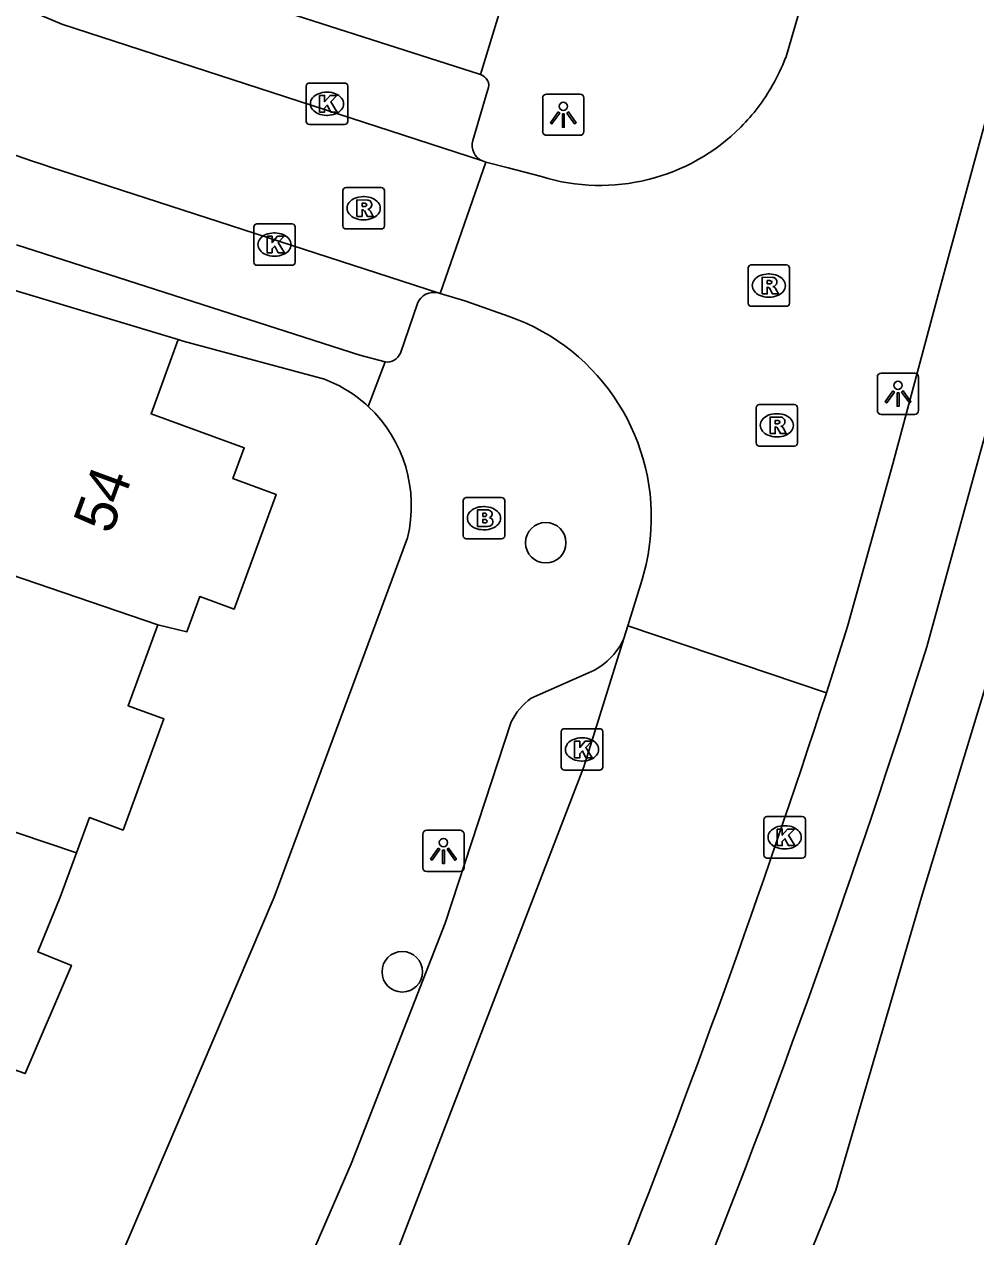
# Model space of a CAD drawing. Extents: x 162542 to 163144, y 380786 to 381511.
# Drawn here: x 163065.29 to 163088.28, y 380991.8 to 381021.08 of the extents above; entities that cross this region are included whole.
import ezdxf

# ---------------------------------------------------------------- set-up
doc = ezdxf.new("R2010")
doc.units = 0
for name, color, linetype in [('IMGEO_Berm_groen', 7, 'Continuous'), ('IMGEO_Boom', 7, 'Continuous'), ('IMGEO_Brandkraan', 7, 'Continuous'), ('IMGEO_Kolk', 7, 'Continuous'), ('IMGEO_Lichtpunt', 7, 'Continuous'), ('IMGEO_Pand', 7, 'Continuous'), ('IMGEO_Pand_nummerreeks', 7, 'Continuous'), ('IMGEO_Parkeervlak_open', 7, 'Continuous'), ('IMGEO_Rijbaan_lokaal_open', 7, 'Continuous'), ('IMGEO_Rioolput', 7, 'Continuous'), ('IMGEO_Voetpad_open', 7, 'Continuous')]:
    doc.layers.add(name, color=color, linetype=linetype)

msp = doc.modelspace()

# ---------------------------------------------------------------- linework, layer by layer
at = {"layer": 'IMGEO_Berm_groen'}
msp.add_lwpolyline([(163077.516, 380959.974), (163074.43, 380965.619), (163074.1, 380966.465), (163073.95, 380967.815), (163074.225, 380969.146), (163074.714, 380970.08), (163079.391, 380979.871), (163082.225, 380986.346), (163084.894, 380992.933), (163086.964, 381000), (163089.194, 381007.335), (163094.981, 381005.761)], dxfattribs=at)
at = {"layer": 'IMGEO_Boom'}
for centre in [(163077.888, 381008.559), (163074.424, 380998.201)]:
    msp.add_circle(centre, 0.489, dxfattribs=at)
at = {"layer": 'IMGEO_Brandkraan'}
for p, q in [((163075.896, 381008.725), (163075.896, 381009.577)), ((163075.971, 381009.651), (163076.823, 381009.651)), ((163076.897, 381009.577), (163076.897, 381008.725)), ((163076.384, 381009.431), (163076.409, 381009.431)), ((163076.823, 381008.651), (163075.971, 381008.651)), ((163076.407, 381008.871), (163076.382, 381008.871))]:
    msp.add_line(p, q, dxfattribs=at)
for points in [[(163075.896, 381008.725), (163075.896, 381009.577)], [(163075.971, 381009.651), (163076.823, 381009.651)], [(163076.897, 381009.577), (163076.897, 381008.725)], [(163076.244, 381009.351), (163076.244, 381008.951), (163076.457, 381008.951)], [(163076.475, 381009.351), (163076.244, 381009.351)], [(163076.423, 381009.27), (163076.369, 381009.27), (163076.369, 381009.194)], [(163076.369, 381009.194), (163076.422, 381009.194)], [(163076.431, 381009.118), (163076.369, 381009.118), (163076.369, 381009.037)], [(163076.369, 381009.037), (163076.431, 381009.037)], [(163076.823, 381008.651), (163075.971, 381008.651)]]:
    msp.add_lwpolyline(points, dxfattribs=at)
for centre, radius, start, end in [((163075.973, 381009.575), 0.0765, 91.552, 178.448), ((163075.973, 381009.575), 0.0765, 91.552, 178.448), ((163076.821, 381009.575), 0.0765, 1.552, 88.448), ((163076.821, 381009.575), 0.0765, 1.552, 88.448), ((163076.424, 381009.232), 0.0379, 267.8285, 90.9355), ((163076.479, 381009.206), 0.145, 59.4692, 91.5367), ((163076.504, 381009.253), 0.0922, 285.5137, 58.1501), ((163076.432, 381009.077), 0.0404, 269.8759, 90.5077), ((163076.463, 381009.202), 0.251, 268.6676, 293.5347), ((163076.509, 381009.061), 0.105, 301.3115, 78.989), ((163075.973, 381008.727), 0.0765, 181.552, 268.448), ((163075.973, 381008.727), 0.0765, 181.552, 268.448), ((163076.821, 381008.727), 0.0765, 271.552, 358.448), ((163076.821, 381008.727), 0.0765, 271.552, 358.448)]:
    msp.add_arc(centre, radius, start, end, dxfattribs=at)
for centre, major_axis, ratio, start_param, end_param in [((163076.383, 381009.151), (-0.387, 0.002), 0.722429, 4.712389, 7.853982), ((163076.408, 381009.151), (-0.39, 0.002), 0.717154, 1.570796, 4.712389)]:
    msp.add_ellipse(centre, major_axis=major_axis, ratio=ratio, start_param=start_param, end_param=end_param, dxfattribs=at)
at = {"layer": 'IMGEO_Kolk'}
for p, q in [((163072.105, 381018.729), (163072.105, 381019.581)), ((163072.18, 381019.655), (163073.032, 381019.655)), ((163073.106, 381019.581), (163073.106, 381018.729)), ((163072.593, 381019.435), (163072.618, 381019.435)), ((163073.032, 381018.655), (163072.18, 381018.655)), ((163072.616, 381018.875), (163072.591, 381018.875)), ((163070.912, 381016.257), (163071.764, 381016.257)), ((163070.837, 381015.331), (163070.837, 381016.183)), ((163071.325, 381016.037), (163071.35, 381016.037)), ((163071.838, 381016.183), (163071.838, 381015.331)), ((163071.348, 381015.477), (163071.323, 381015.477)), ((163071.764, 381015.257), (163070.912, 381015.257)), ((163078.265, 381003.142), (163078.265, 381003.994)), ((163078.34, 381004.068), (163079.192, 381004.068)), ((163079.266, 381003.994), (163079.266, 381003.142)), ((163078.753, 381003.848), (163078.778, 381003.848)), ((163078.776, 381003.288), (163078.751, 381003.288)), ((163079.192, 381003.068), (163078.34, 381003.068)), ((163083.233, 381001.947), (163084.085, 381001.947)), ((163083.158, 381001.021), (163083.158, 381001.873)), ((163083.646, 381001.727), (163083.671, 381001.727)), ((163084.159, 381001.873), (163084.159, 381001.021)), ((163083.669, 381001.167), (163083.644, 381001.167)), ((163084.085, 381000.947), (163083.233, 381000.947))]:
    msp.add_line(p, q, dxfattribs=at)
for points in [[(163072.105, 381018.729), (163072.105, 381019.581)], [(163072.18, 381019.655), (163073.032, 381019.655)], [(163073.106, 381019.581), (163073.106, 381018.729)], [(163072.426, 381019.355), (163072.549, 381019.355), (163072.549, 381019.204), (163072.679, 381019.355), (163072.843, 381019.355), (163072.697, 381019.204), (163072.85, 381018.955), (163072.698, 381018.955), (163072.613, 381019.119), (163072.549, 381019.052), (163072.549, 381018.955), (163072.426, 381018.955), (163072.426, 381019.355)], [(163073.032, 381018.655), (163072.18, 381018.655)], [(163070.912, 381016.257), (163071.764, 381016.257)], [(163070.837, 381015.331), (163070.837, 381016.183)], [(163071.158, 381015.957), (163071.281, 381015.957), (163071.281, 381015.806), (163071.411, 381015.957), (163071.575, 381015.957), (163071.429, 381015.806), (163071.582, 381015.557), (163071.43, 381015.557), (163071.345, 381015.721), (163071.281, 381015.654), (163071.281, 381015.557), (163071.158, 381015.557), (163071.158, 381015.957)], [(163071.838, 381016.183), (163071.838, 381015.331)], [(163071.764, 381015.257), (163070.912, 381015.257)], [(163078.265, 381003.142), (163078.265, 381003.994)], [(163078.34, 381004.068), (163079.192, 381004.068)], [(163079.266, 381003.994), (163079.266, 381003.142)], [(163078.586, 381003.768), (163078.709, 381003.768), (163078.709, 381003.617), (163078.839, 381003.768), (163079.003, 381003.768), (163078.857, 381003.617), (163079.01, 381003.368), (163078.858, 381003.368), (163078.773, 381003.532), (163078.709, 381003.465), (163078.709, 381003.368), (163078.586, 381003.368), (163078.586, 381003.768)], [(163079.192, 381003.068), (163078.34, 381003.068)], [(163083.233, 381001.947), (163084.085, 381001.947)], [(163083.158, 381001.021), (163083.158, 381001.873)], [(163083.479, 381001.647), (163083.602, 381001.647), (163083.602, 381001.496), (163083.732, 381001.647), (163083.896, 381001.647), (163083.75, 381001.496), (163083.903, 381001.247), (163083.751, 381001.247), (163083.666, 381001.411), (163083.602, 381001.344), (163083.602, 381001.247), (163083.479, 381001.247), (163083.479, 381001.647)], [(163084.159, 381001.873), (163084.159, 381001.021)], [(163084.085, 381000.947), (163083.233, 381000.947)]]:
    msp.add_lwpolyline(points, dxfattribs=at)
for centre, start, end in [((163072.182, 381019.579), 91.552, 178.448), ((163072.182, 381019.579), 91.552, 178.448), ((163073.03, 381019.579), 1.552, 88.448), ((163073.03, 381019.579), 1.552, 88.448), ((163072.182, 381018.731), 181.552, 268.448), ((163072.182, 381018.731), 181.552, 268.448), ((163073.03, 381018.731), 271.552, 358.448), ((163073.03, 381018.731), 271.552, 358.448), ((163070.914, 381016.181), 91.552, 178.448), ((163070.914, 381016.181), 91.552, 178.448), ((163071.762, 381016.181), 1.552, 88.448), ((163071.762, 381016.181), 1.552, 88.448), ((163070.914, 381015.333), 181.552, 268.448), ((163070.914, 381015.333), 181.552, 268.448), ((163071.762, 381015.333), 271.552, 358.448), ((163071.762, 381015.333), 271.552, 358.448), ((163078.342, 381003.992), 91.552, 178.448), ((163078.342, 381003.992), 91.552, 178.448), ((163079.19, 381003.992), 1.552, 88.448), ((163079.19, 381003.992), 1.552, 88.448), ((163078.342, 381003.144), 181.552, 268.448), ((163078.342, 381003.144), 181.552, 268.448), ((163079.19, 381003.144), 271.552, 358.448), ((163079.19, 381003.144), 271.552, 358.448), ((163083.235, 381001.871), 91.552, 178.448), ((163083.235, 381001.871), 91.552, 178.448), ((163084.083, 381001.871), 1.552, 88.448), ((163084.083, 381001.871), 1.552, 88.448), ((163083.235, 381001.023), 181.552, 268.448), ((163083.235, 381001.023), 181.552, 268.448), ((163084.083, 381001.023), 271.552, 358.448), ((163084.083, 381001.023), 271.552, 358.448)]:
    msp.add_arc(centre, 0.0765, start, end, dxfattribs=at)
for centre, major_axis, ratio, start_param, end_param in [((163072.592, 381019.155), (-0.387, 0.002), 0.722429, 4.712389, 7.853982), ((163072.617, 381019.155), (-0.39, 0.002), 0.717154, 1.570796, 4.712389), ((163071.324, 381015.757), (-0.387, 0.002), 0.722429, 4.712389, 7.853982), ((163071.349, 381015.757), (-0.39, 0.002), 0.717154, 1.570796, 4.712389), ((163078.752, 381003.568), (-0.387, 0.002), 0.722429, 4.712389, 7.853982), ((163078.777, 381003.568), (-0.39, 0.002), 0.717154, 1.570796, 4.712389), ((163083.645, 381001.447), (-0.387, 0.002), 0.722429, 4.712389, 7.853982), ((163083.67, 381001.447), (-0.39, 0.002), 0.717154, 1.570796, 4.712389)]:
    msp.add_ellipse(centre, major_axis=major_axis, ratio=ratio, start_param=start_param, end_param=end_param, dxfattribs=at)
at = {"layer": 'IMGEO_Lichtpunt'}
for p, q in [((163077.815, 381019.295), (163077.815, 381018.488)), ((163077.815, 381019.295), (163077.815, 381018.488)), ((163078.717, 381019.39), (163077.909, 381019.39)), ((163078.717, 381019.39), (163077.909, 381019.39)), ((163078.811, 381018.488), (163078.811, 381019.295)), ((163078.811, 381018.488), (163078.811, 381019.295)), ((163077.909, 381018.394), (163078.717, 381018.394)), ((163077.909, 381018.394), (163078.717, 381018.394)), ((163085.899, 381012.559), (163085.899, 381011.752)), ((163085.899, 381012.559), (163085.899, 381011.752)), ((163086.801, 381012.654), (163085.993, 381012.654)), ((163086.801, 381012.654), (163085.993, 381012.654)), ((163086.895, 381011.752), (163086.895, 381012.559)), ((163086.895, 381011.752), (163086.895, 381012.559)), ((163085.993, 381011.658), (163086.801, 381011.658)), ((163085.993, 381011.658), (163086.801, 381011.658)), ((163075.821, 381001.617), (163075.013, 381001.617)), ((163075.821, 381001.617), (163075.013, 381001.617)), ((163074.919, 381001.522), (163074.919, 381000.715)), ((163074.919, 381001.522), (163074.919, 381000.715)), ((163075.915, 381000.715), (163075.915, 381001.522)), ((163075.915, 381000.715), (163075.915, 381001.522)), ((163075.013, 381000.621), (163075.821, 381000.621)), ((163075.013, 381000.621), (163075.821, 381000.621))]:
    msp.add_line(p, q, dxfattribs=at)
for points in [[(163078.189, 381018.959), (163078.228, 381018.931), (163078.04, 381018.669), (163078.002, 381018.696), (163078.189, 381018.959)], [(163078.291, 381018.911), (163078.338, 381018.911), (163078.338, 381018.589), (163078.291, 381018.589), (163078.291, 381018.911)], [(163078.401, 381018.931), (163078.439, 381018.958), (163078.626, 381018.696), (163078.587, 381018.668), (163078.401, 381018.931)], [(163086.273, 381012.223), (163086.312, 381012.195), (163086.124, 381011.933), (163086.086, 381011.96), (163086.273, 381012.223)], [(163086.375, 381012.175), (163086.422, 381012.175), (163086.422, 381011.853), (163086.375, 381011.853), (163086.375, 381012.175)], [(163086.485, 381012.195), (163086.523, 381012.222), (163086.71, 381011.96), (163086.671, 381011.932), (163086.485, 381012.195)], [(163075.293, 381001.186), (163075.332, 381001.158), (163075.144, 381000.896), (163075.106, 381000.923), (163075.293, 381001.186)], [(163075.395, 381001.138), (163075.442, 381001.138), (163075.442, 381000.816), (163075.395, 381000.816), (163075.395, 381001.138)], [(163075.505, 381001.158), (163075.543, 381001.185), (163075.73, 381000.923), (163075.691, 381000.895), (163075.505, 381001.158)]]:
    msp.add_lwpolyline(points, dxfattribs=at)
for centre in [(163078.314, 381019.093), (163086.398, 381012.357), (163075.418, 381001.32)]:
    msp.add_circle(centre, 0.0994, dxfattribs=at)
for centre, start, end in [((163077.909, 381019.295), 90, 180), ((163077.909, 381019.295), 90, 180), ((163078.717, 381019.295), 0, 90), ((163078.717, 381019.295), 0, 90), ((163077.909, 381018.488), 180, 270), ((163077.909, 381018.488), 180, 270), ((163078.717, 381018.488), 270, 0), ((163078.717, 381018.488), 270, 360), ((163085.993, 381012.559), 90, 180), ((163085.993, 381012.559), 90, 180), ((163086.801, 381012.559), 0, 90), ((163086.801, 381012.559), 0, 90), ((163085.993, 381011.752), 180, 270), ((163085.993, 381011.752), 180, 270), ((163086.801, 381011.752), 270, 0), ((163086.801, 381011.752), 270, 360), ((163075.013, 381001.522), 90, 180), ((163075.013, 381001.522), 90, 180), ((163075.821, 381001.522), 0, 90), ((163075.821, 381001.522), 0, 90), ((163075.013, 381000.715), 180, 270), ((163075.013, 381000.715), 180, 270), ((163075.821, 381000.715), 270, 0), ((163075.821, 381000.715), 270, 360)]:
    msp.add_arc(centre, 0.0946, start, end, dxfattribs=at)
at = {"layer": 'IMGEO_Pand'}
for points in [[(163058.425, 381016.641), (163059.788, 381016.232), (163069.013, 381013.461)], [(163068.518, 381006.576), (163069.221, 381006.408), (163069.534, 381007.26), (163070.362, 381006.956), (163071.38, 381009.724), (163070.334, 381010.108), (163070.605, 381010.846), (163068.355, 381011.673), (163069.013, 381013.461)], [(163057.81, 381010.232), (163068.518, 381006.576)], [(163068.518, 381006.576), (163067.8, 381004.624), (163068.668, 381004.305), (163067.682, 381001.622), (163066.867, 381001.922), (163066.554, 381001.07)], [(163055.826, 381004.685), (163066.554, 381001.07)], [(163066.554, 381001.07), (163066.16, 381000), (163065.623, 380998.68), (163066.431, 380998.356), (163065.317, 380995.743), (163064.6, 380995.997), (163064.442, 380995.619)]]:
    msp.add_lwpolyline(points, dxfattribs=at)
at = {"layer": 'IMGEO_Parkeervlak_open'}
msp.add_lwpolyline([(163089.453, 381014.635), (163089.294, 381014.047), (163088.512, 381011.194), (163087.092, 381006.049)], dxfattribs=at)
msp.add_arc((162878.42, 381071.645), 218.74, 338.09649, 342.5496, dxfattribs=at)
at = {"layer": 'IMGEO_Rijbaan_lokaal_open'}
for points in [[(163084.522, 381023.155), (163083.684, 381020.268)], [(163084.668, 381004.939), (163085.179, 381006.534), (163086.271, 381010.462), (163087.365, 381014.541), (163089.373, 381021.916)], [(163066.198, 381021.075), (163076.358, 381017.775)], [(163076.443, 381017.747), (163075.34, 381014.574)], [(163076.358, 381017.775), (163076.443, 381017.747)], [(163077.789, 381017.396), (163076.984, 381017.606), (163076.443, 381017.747)], [(163066.18, 381017.547), (163075.29, 381014.59)], [(163075.34, 381014.574), (163075.29, 381014.59)], [(163075.34, 381014.574), (163075.933, 381014.401), (163076.094, 381014.344), (163077.006, 381014.021)], [(163080.215, 381007.669), (163079.872, 381006.55)], [(163079.779, 381006.247), (163079.872, 381006.55)], [(163079.872, 381006.55), (163084.668, 381004.939)], [(163079.779, 381006.247), (163078.808, 381003.149), (163072.993, 380988.071)]]:
    msp.add_lwpolyline(points, dxfattribs=at)
for centre, radius, start, end in [((163077.641, 381048.539), 29.753, 219.7527, 247.3802), ((163074.034, 381042.707), 26.358, 235.8787, 252.6631), ((163079.133, 381022.02), 4.876, 330.2987, 338.9422), ((163079.289, 381021.913), 4.688, 314.9339, 330.4958), ((163079.2, 381021.989), 4.805, 252.9213, 315.0447), ((163075.297, 381009.171), 5.142, 354.1044, 70.5895), ((163075.289, 381009.172), 5.15, 343.0291, 354.1022), ((162863.597, 381076.707), 232.428, 338.26932, 342.01453)]:
    msp.add_arc(centre, radius, start, end, dxfattribs=at)
at = {"layer": 'IMGEO_Rioolput'}
for p, q in [((163073.066, 381017.134), (163073.918, 381017.134)), ((163072.991, 381016.208), (163072.991, 381017.06)), ((163073.479, 381016.914), (163073.504, 381016.914)), ((163073.992, 381017.06), (163073.992, 381016.208)), ((163073.502, 381016.354), (163073.477, 381016.354)), ((163073.918, 381016.134), (163073.066, 381016.134)), ((163082.777, 381014.341), (163082.777, 381015.193)), ((163082.852, 381015.267), (163083.704, 381015.267)), ((163083.778, 381015.193), (163083.778, 381014.341)), ((163083.265, 381015.047), (163083.29, 381015.047)), ((163083.288, 381014.487), (163083.263, 381014.487)), ((163083.704, 381014.267), (163082.852, 381014.267)), ((163083.045, 381011.893), (163083.897, 381011.893)), ((163082.97, 381010.967), (163082.97, 381011.819)), ((163083.458, 381011.673), (163083.483, 381011.673)), ((163083.971, 381011.819), (163083.971, 381010.967)), ((163083.481, 381011.113), (163083.456, 381011.113)), ((163083.897, 381010.893), (163083.045, 381010.893))]:
    msp.add_line(p, q, dxfattribs=at)
for points in [[(163073.066, 381017.134), (163073.918, 381017.134)], [(163072.991, 381016.208), (163072.991, 381017.06)], [(163073.58, 381016.832), (163073.328, 381016.834), (163073.328, 381016.434)], [(163073.992, 381017.06), (163073.992, 381016.208)], [(163073.328, 381016.434), (163073.452, 381016.434), (163073.452, 381016.596), (163073.463, 381016.596)], [(163073.506, 381016.753), (163073.452, 381016.753), (163073.452, 381016.672)], [(163073.452, 381016.672), (163073.504, 381016.672)], [(163073.51, 381016.567), (163073.581, 381016.434), (163073.721, 381016.434), (163073.656, 381016.56)], [(163073.918, 381016.134), (163073.066, 381016.134)], [(163082.777, 381014.341), (163082.777, 381015.193)], [(163082.852, 381015.267), (163083.704, 381015.267)], [(163083.778, 381015.193), (163083.778, 381014.341)], [(163083.366, 381014.965), (163083.114, 381014.967), (163083.114, 381014.567)], [(163083.292, 381014.886), (163083.238, 381014.886), (163083.238, 381014.805)], [(163083.238, 381014.805), (163083.29, 381014.805)], [(163083.114, 381014.567), (163083.238, 381014.567), (163083.238, 381014.729), (163083.249, 381014.729)], [(163083.296, 381014.7), (163083.367, 381014.567), (163083.507, 381014.567), (163083.442, 381014.693)], [(163083.704, 381014.267), (163082.852, 381014.267)], [(163083.045, 381011.893), (163083.897, 381011.893)], [(163082.97, 381010.967), (163082.97, 381011.819)], [(163083.559, 381011.591), (163083.307, 381011.593), (163083.307, 381011.193)], [(163083.971, 381011.819), (163083.971, 381010.967)], [(163083.307, 381011.193), (163083.431, 381011.193), (163083.431, 381011.355), (163083.442, 381011.355)], [(163083.485, 381011.512), (163083.431, 381011.512), (163083.431, 381011.431)], [(163083.431, 381011.431), (163083.483, 381011.431)], [(163083.489, 381011.326), (163083.56, 381011.193), (163083.7, 381011.193), (163083.635, 381011.319)], [(163083.897, 381010.893), (163083.045, 381010.893)]]:
    msp.add_lwpolyline(points, dxfattribs=at)
for centre, radius, start, end in [((163073.068, 381017.058), 0.0765, 91.552, 178.448), ((163073.068, 381017.058), 0.0765, 91.552, 178.448), ((163073.916, 381017.058), 0.0765, 1.552, 88.448), ((163073.916, 381017.058), 0.0765, 1.552, 88.448), ((163073.579, 381016.722), 0.109, 350.3612, 89.416), ((163073.462, 381016.543), 0.0533, 26.0293, 88.6989), ((163073.488, 381016.861), 0.19, 274.7715, 282.9687), ((163073.512, 381016.657), 0.0964, 77.0061, 93.1865), ((163073.526, 381016.714), 0.0378, 276.6634, 79.6772), ((163073.577, 381016.722), 0.112, 277.5842, 350.9817), ((163073.561, 381016.507), 0.108, 29.5134, 73.7905), ((163073.068, 381016.21), 0.0765, 181.552, 268.448), ((163073.068, 381016.21), 0.0765, 181.552, 268.448), ((163073.916, 381016.21), 0.0765, 271.552, 358.448), ((163073.916, 381016.21), 0.0765, 271.552, 358.448), ((163082.854, 381015.191), 0.0765, 91.552, 178.448), ((163082.854, 381015.191), 0.0765, 91.552, 178.448), ((163083.702, 381015.191), 0.0765, 1.552, 88.448), ((163083.702, 381015.191), 0.0765, 1.552, 88.448), ((163083.274, 381014.994), 0.19, 274.7715, 282.9687), ((163083.298, 381014.79), 0.0964, 77.0061, 93.1865), ((163083.312, 381014.847), 0.0378, 276.6634, 79.6772), ((163083.365, 381014.855), 0.109, 350.3612, 89.416), ((163083.363, 381014.855), 0.112, 277.5842, 350.9817), ((163083.248, 381014.676), 0.0533, 26.0293, 88.6989), ((163083.347, 381014.64), 0.108, 29.5134, 73.7905), ((163082.854, 381014.343), 0.0765, 181.552, 268.448), ((163082.854, 381014.343), 0.0765, 181.552, 268.448), ((163083.702, 381014.343), 0.0765, 271.552, 358.448), ((163083.702, 381014.343), 0.0765, 271.552, 358.448), ((163083.047, 381011.817), 0.0765, 91.552, 178.448), ((163083.047, 381011.817), 0.0765, 91.552, 178.448), ((163083.895, 381011.817), 0.0765, 1.552, 88.448), ((163083.895, 381011.817), 0.0765, 1.552, 88.448), ((163083.558, 381011.481), 0.109, 350.3612, 89.416), ((163083.441, 381011.302), 0.0533, 26.0293, 88.6989), ((163083.467, 381011.62), 0.19, 274.7715, 282.9687), ((163083.491, 381011.416), 0.0964, 77.0061, 93.1865), ((163083.505, 381011.473), 0.0378, 276.6634, 79.6772), ((163083.556, 381011.481), 0.112, 277.5842, 350.9817), ((163083.54, 381011.266), 0.108, 29.5134, 73.7905), ((163083.047, 381010.969), 0.0765, 181.552, 268.448), ((163083.047, 381010.969), 0.0765, 181.552, 268.448), ((163083.895, 381010.969), 0.0765, 271.552, 358.448), ((163083.895, 381010.969), 0.0765, 271.552, 358.448)]:
    msp.add_arc(centre, radius, start, end, dxfattribs=at)
for centre, major_axis, ratio, start_param, end_param in [((163073.478, 381016.634), (-0.387, 0.002), 0.722429, 4.712389, 7.853982), ((163073.503, 381016.634), (-0.39, 0.002), 0.717154, 1.570796, 4.712389), ((163083.264, 381014.767), (-0.387, 0.002), 0.722429, 4.712389, 7.853982), ((163083.289, 381014.767), (-0.39, 0.002), 0.717154, 1.570796, 4.712389), ((163083.457, 381011.393), (-0.387, 0.002), 0.722429, 4.712389, 7.853982), ((163083.482, 381011.393), (-0.39, 0.002), 0.717154, 1.570796, 4.712389)]:
    msp.add_ellipse(centre, major_axis=major_axis, ratio=ratio, start_param=start_param, end_param=end_param, dxfattribs=at)
at = {"layer": 'IMGEO_Voetpad_open'}
for points in [[(163077.265, 381022.975), (163076.311, 381019.863)], [(163076.311, 381019.863), (163066.831, 381022.9)], [(163076.494, 381019.496), (163076.128, 381018.267)], [(163074.007, 381012.924), (163073.398, 381013.088), (163065.109, 381015.747)], [(163074.789, 381014.333), (163074.379, 381013.136)], [(163069.013, 381013.461), (163069.135, 381013.428), (163072.548, 381012.505)], [(163073.601, 381011.848), (163074.007, 381012.924)], [(163074.549, 381008.679), (163071.327, 381000), (163065.476, 380986.302)], [(163077.538, 381004.804), (163078.925, 381005.416)], [(163071.137, 380988.842), (163073.192, 380993.563), (163075.459, 380999.371), (163077.054, 381004.231)]]:
    msp.add_lwpolyline(points, dxfattribs=at)
for centre, radius, start, end in [((163076.232, 381019.594), 0.28, 339.4531, 73.552), ((163076.527, 381018.154), 0.415, 164.2055, 245.9047), ((163075.187, 381014.175), 0.428, 76.0152, 158.2981), ((163074.053, 381013.275), 0.354, 262.469, 336.888), ((163071.378, 381009.457), 3.265, 47.0818, 68.9955), ((163071.377, 381009.457), 3.266, 346.226, 47.0829), ((163078.258, 381006.956), 1.678, 293.4204, 335.0155), ((163078.441, 381003.551), 1.545, 125.762, 153.8639)]:
    msp.add_arc(centre, radius, start, end, dxfattribs=at)

# ---------------------------------------------------------------- texts
at = {"layer": 'IMGEO_Pand_nummerreeks'}
msp.add_text('54', height=1, rotation=69.8264, dxfattribs=at).set_placement((163067.392, 381008.737))

doc.saveas('drawing.dxf')
